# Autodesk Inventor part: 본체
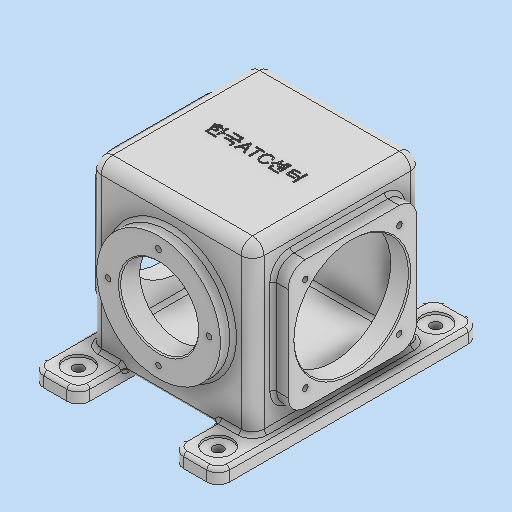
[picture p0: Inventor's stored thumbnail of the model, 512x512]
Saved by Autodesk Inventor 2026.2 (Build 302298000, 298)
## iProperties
Created: 2026-01
Part Number: 본체
Material: 일반
Document SubType Name: Modeling
Designer: PC2-07
Density: 1 g/cm^3
Appearance: 기본값
Mass: 901.565 g
Surface Area: 2483.61 cm^2
Volume: 901.565 cm^3
Author: PC2-07
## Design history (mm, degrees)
sketch "스케치1"
  geometry: L1 (-71, 74)-(71, 74); L2 (71, 74)-(71, -74); L3 (71, -74)-(-71, -74); L4 (-71, -74)-(-71, 74); L5 (-71, 74)-(71, -74); L6 (71, 74)-(-71, -74); L7 (0, 105.69)-(0, -105.69); L8 (-81, -70)-(-41, -70); L9 (-41, -70)-(-41, -82); L10 (-41, -82)-(-81, -82); L11 (-81, -82)-(-81, -70); L12 (81, -70)-(41, -70); L13 (41, -70)-(41, -82); L14 (41, -82)-(81, -82); L15 (81, -82)-(81, -70); 3 further points
  constraints: 30 end point, 5 symmetric about line, 4 parallel, 3 midpoint, 2 horizontal, 2 perpendicular, 1 point on line, 1 vertical
  dimensions: "d0" = 142 distance of L2.end L3.end; "d1" = 148 distance of L1.end L2.end; "d54" = 8 distance between parallel lines of L3 L10; "d55" = 12 distance of L10.end L8.start; "d56" = 40 distance of L9.end L10.end; "d57" = 162 distance between parallel lines of L11 L15
extrude "돌출1" new body sketch "스케치1" stored distance "d6" = 148; taper "d7" = 0 deg
sketch "스케치2"
  geometry: C1 r 54 at (0, 0); 1 further point
  constraints: 1 centre point, 1 coincident
  dimensions: "d10" = 108 diameter of C1
extrude "돌출3" join sketch "스케치2" distance "d11" = 11; taper "d12" = 0 deg
node "작업 평면1"
sketch "스케치3"
  geometry: L1 (141.5, -6.5)-(6.5, -6.5); L2 (6.5, -6.5)-(6.5, -141.5); L3 (6.5, -141.5)-(141.5, -141.5); L4 (141.5, -141.5)-(141.5, -6.5); L5 (141.5, -6.5)-(6.5, -141.5); L6 (6.5, -6.5)-(141.5, -141.5); 1 further point
  constraints: 12 end point, 2 midpoint, 2 parallel, 1 horizontal, 1 perpendicular
  dimensions: "d14" = 135 distance of L3.end L2.end; "d15" = 135 distance of L2.end L1.end
extrude "돌출4" cut sketch "스케치3" stored distance "d16" = 135; taper "d17" = 0 deg
sketch "스케치4"
  geometry: C1 r 34 at (0, 0); 1 further point
  constraints: 1 centre point, 1 coincident
  dimensions: "d18" = 68 diameter of C1
extrude "돌출5" cut sketch "스케치4" distance "d19" = 86; taper "d20" = 0 deg
sketch "스케치5"
  geometry: A1 r 44 centre (0, 0) between (0, 44) and (44, 0); 3 further points
  constraints: 4 point on circle, 1 centre point, 1 coincident
  dimensions: "d21" = 88 diameter of A1
hole "구멍1" sketch "스케치5" at (0, -44), (-44, 0), (0, 44), (44, 0) diameter "d22" = 4.917; stored, may be unused: countersink angle "d26" = 90 deg, drill point angle "d28" = 118 deg; dims "d23" = 12, "d24" = 10, "d25" = 2, "d27" = 14
sketch "스케치6"
  geometry: L1 (18, -18)-(130, -18); L2 (130, -18)-(130, -130); L3 (130, -130)-(18, -130); L4 (18, -130)-(18, -18); L5 (18, -18)-(130, -130); L6 (130, -18)-(18, -130); 1 further point
  constraints: 12 end point, 2 midpoint, 2 parallel, 1 horizontal, 1 perpendicular
  dimensions: "d29" = 112 distance of L2.end L3.end; "d30" = 112 distance of L1.end L2.end
extrude "돌출6" join sketch "스케치6" distance "d31" = 13; taper "d32" = 0 deg
sketch "스케치7"
  geometry: C1 r 50 at (74, -74); 1 further point
  constraints: 1 centre point, 1 coincident
  dimensions: "d33" = 100 diameter of C1
extrude "돌출7" cut sketch "스케치7" distance "d34" = 79.25; taper "d35" = 0 deg
fillet "모깎기1" dims "d36" = 15
fillet "모깎기2" dims "d37" = 3
sketch "스케치8"
  geometry: L1 (33, -33)-(115, -33); L2 (115, -33)-(115, -115); L3 (115, -115)-(33, -115); L4 (33, -115)-(33, -33); L5 (33, -33)-(115, -115); L6 (115, -33)-(33, -115); 5 further points
  constraints: 12 end point, 4 coincident, 2 midpoint, 2 parallel, 1 horizontal, 1 perpendicular
  dimensions: "d38" = 82 distance of L2.end L3.end; "d39" = 82 distance of L1.end L2.end
hole "구멍2" sketch "스케치8" at (33, -33), (115, -33), (115, -115), (33, -115) diameter "d40" = 4.917; stored, may be unused: countersink angle "d44" = 90 deg, drill point angle "d46" = 118 deg; dims "d41" = 12, "d42" = 4, "d43" = 2, "d45" = 14
fillet "모깎기3" dims "d47" = 3
fillet "모깎기4" dims "d48" = 10
fillet "모깎기5" dims "d49" = 10
extrude "돌출8" join sketch "스케치1" stored distance "d58" = 228; taper "d59" = 0 deg
fillet "모깎기8" dims "d60" = 10
fillet "모깎기9" dims "d61" = 3
sketch "스케치9"
  geometry: L1 (10, -30)-(132, -30); L2 (11.823, 158)-(133.823, 158); L3 (142, 178)-(122, 178) reference; 5 further points
  constraints: 4 coincident, 4 end point, 2 horizontal
  dimensions: "d69" = 188 distance from line of L2 point (132, -30); "d70" = 122 distance of L2.start L2.end; "d71" = 122 distance of L1.start L1.end; "d72" = 20 distance between parallel lines of L3 L2
hole "구멍3" sketch "스케치9" at (10, -30), (132, -30), (133.823, 158), (11.823, 158) diameter "d62" = 9; stored, may be unused: countersink angle "d66" = 90 deg, drill point angle "d68" = 0 deg; dims "d63" = 12, "d64" = 24, "d65" = 2, "d67" = 14
fillet "모깎기10" dims "d73" = 3
fillet "모깎기11" dims "d74" = 3
fillet "모깎기12" dims "d75" = 3
sketch "스케치11"
  geometry: 2 further points
  constraints: 1 coincident, 1 other
feature "엠보싱1" sketch "스케치11" dims "d0" = 142, "d1" = 148, "d54" = 8, "d55" = 12, "d56" = 40, "d57" = 162, "d76" = 0.5, "d77" = 0
chamfer "모따기1" distance "d78" = 1; stored, may be unused: second distance "d79" = 2, angle "d80" = 45 deg
chamfer "모따기2" distance "d81" = 1; stored, may be unused: second distance "d82" = 2, angle "d83" = 45 deg
feature "Ͳ耀ʹ耀Ͷ耀͸耀ͺ耀ͼ耀;耀΀耀" dims "d0" = 142, "d1" = 148, "d6" = 148, "d7" = 0, "d10" = 108, "d11" = 11, "d12" = 0, "d13" = -71, "d14" = 135, "d15" = 135, "d16" = 135, "d17" = 0, "d18" = 68, "d19" = 86, "d20" = 0, "d21" = 88, "d22" = 4.917, "d23" = 12, "d24" = 10, "d25" = 2, "d26" = 90 deg, "d27" = 14, "d28" = 118 deg, "d29" = 112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
node "솔리드1"
mirror "미러1"
feature "A9D066F2-1C7D-4E18-AEED-F7BC21143FA4" dims "d62" = 9, "d63" = 12, "d64" = 24, "d65" = 2, "d66" = 90 deg, "d67" = 14, "d68" = 0
